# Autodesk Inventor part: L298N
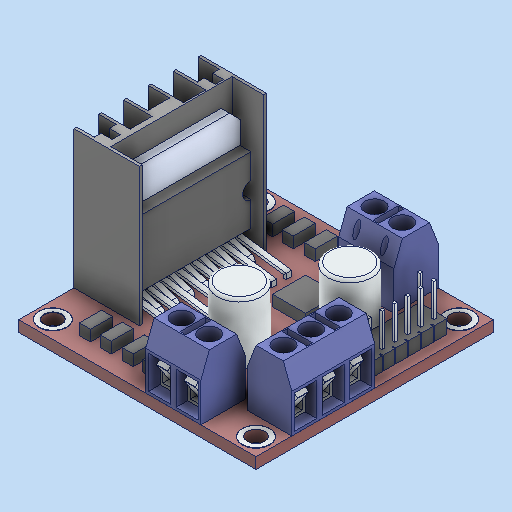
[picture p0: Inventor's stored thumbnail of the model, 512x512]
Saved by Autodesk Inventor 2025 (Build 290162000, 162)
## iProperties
Created: 2020-08
Part Number: L298N
Material: Generico
Document SubType Name: Modeling
Designer: R5800u
Density: 1 g/cm^3
Appearance: Default
Author: R5800u
Sending System: SolidWorks 2018
Last Author: Alexis 18
Last Saved: 2020-08-15
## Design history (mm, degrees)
feature "Saliente-Extruir22"
node "Solido1"
